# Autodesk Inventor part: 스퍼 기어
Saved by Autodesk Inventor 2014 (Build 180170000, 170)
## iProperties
Created: 2026-10
Part Number: 스퍼 기어
Material: 일반
Document SubType Name: Modeling
Designer: dg
Density: 1 g/cm^3
Appearance: 기본값
Author: dg
Author: jhkim
Creation Date: 2026-09-29
Sending System: Autodesk Inventor 2027
Preprocessor: ST-DEVELOPER v20.1
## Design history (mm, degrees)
node "스퍼 기어1"
body "Solid1"
node "기준1"
